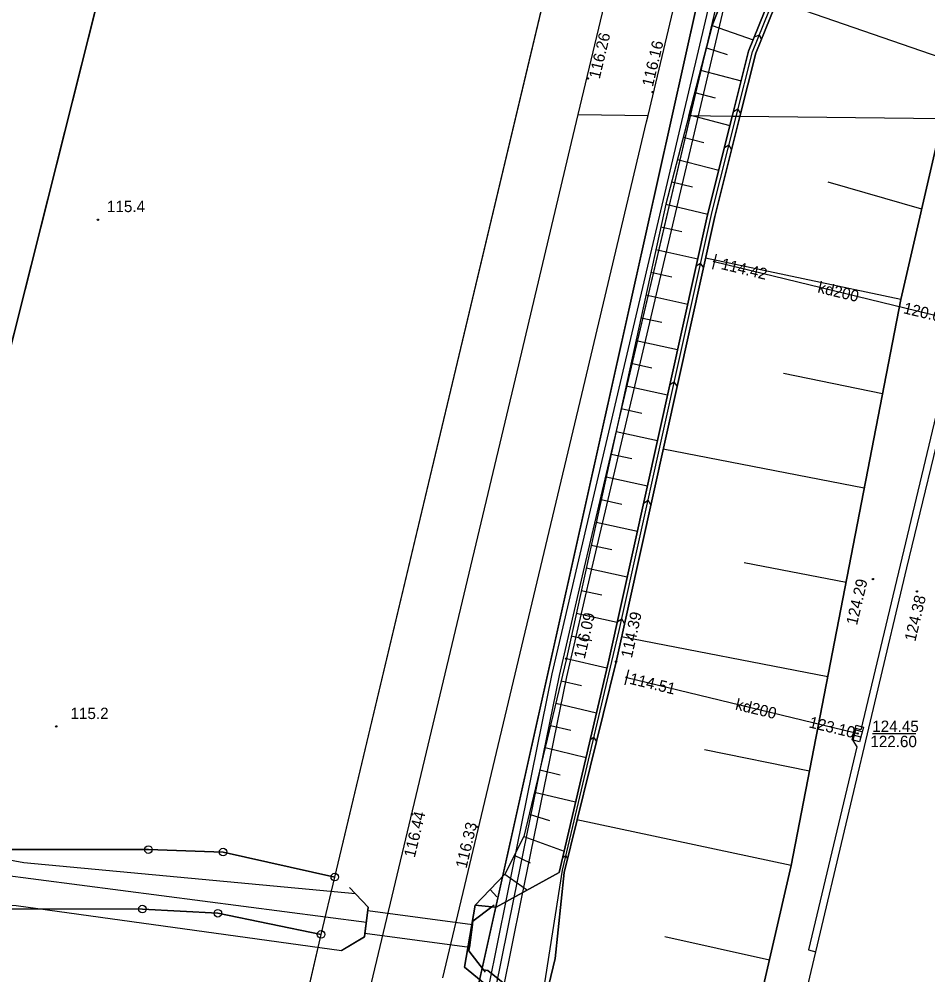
# Model space of a CAD drawing. Extents: x 6424617 to 6425697, y 5665845 to 5667190.
# Drawn here: x 6425223.5 to 6425283.4, y 5666258.5 to 5666321.5 of the extents above; entities that cross this region are included whole.
import ezdxf

# ---------------------------------------------------------------- set-up
doc = ezdxf.new("R2010")
doc.units = 0
for name, color, linetype in [('Warstwa 1', 7, 'Continuous'), ('Warstwa 10', 7, 'Continuous'), ('Warstwa 12', 7, 'Continuous'), ('Warstwa 13', 7, 'Continuous'), ('Warstwa 14', 7, 'Continuous'), ('Warstwa 15', 7, 'Continuous'), ('Warstwa 20', 7, 'Continuous'), ('Warstwa 21', 7, 'Continuous'), ('Warstwa 22', 7, 'Continuous'), ('Warstwa 25', 7, 'Continuous'), ('Warstwa 4', 7, 'Continuous'), ('Warstwa 47', 7, 'Continuous'), ('Warstwa 6', 7, 'Continuous'), ('Warstwa 61', 7, 'Continuous'), ('Warstwa 8', 7, 'Continuous'), ('Warstwa 9', 7, 'Continuous')]:
    doc.layers.add(name, color=color, linetype=linetype)

msp = doc.modelspace()

# ---------------------------------------------------------------- linework, layer by layer
at = {"layer": 'Warstwa 1'}
for p, q in [((6425217.631, 5666278.959), (6425251.855, 5666415.084)), ((6425217.631, 5666278.959), (6425251.855, 5666415.084)), ((6425244.275, 5666264.977), (6425279.037, 5666410.906)), ((6425244.275, 5666264.977), (6425279.037, 5666410.906)), ((6425252.81, 5666253.65), (6425268.93, 5666326.03)), ((6425252.81, 5666253.65), (6425268.93, 5666326.03)), ((6425221.085, 5666266.797), (6425231.986, 5666266.785)), ((6425221.085, 5666266.797), (6425231.986, 5666266.785)), ((6425231.986, 5666266.785), (6425236.914, 5666266.626)), ((6425231.986, 5666266.785), (6425236.914, 5666266.626)), ((6425236.914, 5666266.626), (6425244.275, 5666264.977)), ((6425236.914, 5666266.626), (6425244.275, 5666264.977)), ((6425243.369, 5666261.198), (6425244.275, 5666264.977)), ((6425243.369, 5666261.198), (6425244.275, 5666264.977)), ((6425220.398, 5666262.875), (6425231.589, 5666262.87)), ((6425220.398, 5666262.875), (6425231.589, 5666262.87)), ((6425231.589, 5666262.87), (6425236.566, 5666262.59)), ((6425231.589, 5666262.87), (6425236.566, 5666262.59)), ((6425236.566, 5666262.59), (6425243.369, 5666261.198)), ((6425236.566, 5666262.59), (6425243.369, 5666261.198)), ((6425235.255, 5666226.065), (6425243.369, 5666261.198)), ((6425235.255, 5666226.065), (6425243.369, 5666261.198))]:
    msp.add_line(p, q, dxfattribs=at)
at = {"layer": 'Warstwa 10'}
for points in [[(6425267.728, 5666315.146), (6425271.19, 5666329.86), (6425276.57, 5666352.13), (6425283.28, 5666380.44), (6425290.28, 5666409.92), (6425300.88, 5666454.64), (6425307.494, 5666481.767)], [(6425253.995, 5666253.473), (6425254.27, 5666254.64), (6425254.89, 5666257.65), (6425256.08, 5666263.53), (6425259.08, 5666278.27), (6425260.73, 5666285.4), (6425267.728, 5666315.146)], [(6425245.24, 5666264.28), (6425246.48, 5666262.99), (6425246.23, 5666261.04), (6425244.69, 5666260.12)], [(6425254.2, 5666258.71), (6425253.12, 5666260.12), (6425253.37, 5666262.07), (6425254.79, 5666263.15)]]:
    msp.add_lwpolyline(points, dxfattribs=at)
for centre in [(6425231.986, 5666266.785), (6425231.986, 5666266.785), (6425236.914, 5666266.626), (6425236.914, 5666266.626), (6425244.275, 5666264.977), (6425244.275, 5666264.977), (6425231.589, 5666262.87), (6425236.566, 5666262.59), (6425243.369, 5666261.198), (6425243.369, 5666261.198)]:
    msp.add_circle(centre, 0.25, dxfattribs=at)
at = {"layer": 'Warstwa 12'}
for points in [[(6425269.29, 5666305.54), (6425285.02, 5666301.73), (6425285.27, 5666301.67)], [(6425263.52, 5666278.14), (6425278.51, 5666274.5), (6425278.75, 5666274.44)]]:
    msp.add_lwpolyline(points, dxfattribs=at)
at = {"layer": 'Warstwa 13'}
for centre in [(6425228.656, 5666308.303), (6425225.915, 5666274.903)]:
    msp.add_circle(centre, 0.045, dxfattribs=at)
at = {"layer": 'Warstwa 14'}
msp.add_line((6425282.565, 5666274.414), (6425279.727, 5666274.414), dxfattribs=at)
for centre in [(6425269.29, 5666305.54), (6425263.52, 5666278.14), (6425278.51, 5666274.5), (6425278.75, 5666274.44)]:
    msp.add_circle(centre, 0.045, dxfattribs=at)
at = {"layer": 'Warstwa 20'}
for points in [[(6425292.365, 5666377.252), (6425289.64, 5666377.785), (6425288.462, 5666378.016), (6425285.098, 5666378.674), (6425284.514, 5666374.573), (6425281.056, 5666360.861), (6425274.474, 5666334.861), (6425272.279, 5666329.059), (6425269.154, 5666321.093), (6425267.61, 5666315.147)], [(6425242.611, 5666194.491), (6425255.097, 5666192.415), (6425259.987, 5666203.38), (6425274.357, 5666265.741), (6425281.592, 5666303.052), (6425284.331, 5666314.945)], [(6425267.61, 5666315.147), (6425266.101, 5666309.334), (6425259.538, 5666279.373), (6425256.735, 5666267.65), (6425255.48, 5666265.172), (6425253.533, 5666263.126)], [(6425242.611, 5666194.491), (6425238.381, 5666195.698), (6425239.081, 5666197.896), (6425243.343, 5666206.271), (6425244.956, 5666211.914), (6425249.351, 5666232.612), (6425254.77, 5666257.432), (6425252.819, 5666259.028), (6425253.533, 5666263.126)]]:
    msp.add_lwpolyline(points, dxfattribs=at)
at = {"layer": 'Warstwa 21'}
for p, q in [((6425269.408, 5666306.026), (6425269.172, 5666305.054)), ((6425263.638, 5666278.626), (6425263.402, 5666277.654))]:
    msp.add_line(p, q, dxfattribs=at)
for points in [[(6425270.982, 5666315.107), (6425272.032, 5666319.27), (6425277.811, 5666333.541), (6425285.262, 5666361.705), (6425288.33, 5666373.734), (6425289.376, 5666376.843), (6425292.365, 5666377.252), (6425292.98, 5666380.282), (6425290.684, 5666381.655), (6425291.516, 5666385.64), (6425292.444, 5666389.955), (6425293.272, 5666396.442), (6425293.428, 5666397.92), (6425295.255, 5666405.439), (6425296.508, 5666407.837), (6425298.975, 5666417.006), (6425304.639, 5666439.871), (6425307.108, 5666449.766)], [(6425292.365, 5666377.252), (6425289.376, 5666376.843), (6425288.222, 5666377.14), (6425287.852, 5666373.863), (6425284.784, 5666361.834), (6425277.334, 5666333.689), (6425271.555, 5666319.419), (6425270.472, 5666315.113)], [(6425242.611, 5666194.491), (6425241.54, 5666196.131), (6425241.838, 5666198.266), (6425245.305, 5666204.665), (6425246.454, 5666206.825), (6425247.076, 5666209.095), (6425251.913, 5666231.035), (6425258.791, 5666259.61), (6425259.384, 5666265.281), (6425262.815, 5666279.174), (6425269.317, 5666308.506), (6425270.982, 5666315.107)], [(6425253.533, 5666263.126), (6425254.619, 5666263.02), (6425254.911, 5666262.991), (6425259.063, 5666265.277), (6425262.337, 5666279.282), (6425268.839, 5666308.615), (6425270.472, 5666315.113)], [(6425242.611, 5666194.491), (6425241.54, 5666196.131), (6425240.763, 5666196.325), (6425241.403, 5666198.514), (6425244.869, 5666204.893), (6425245.978, 5666207.014), (6425246.598, 5666209.224), (6425251.435, 5666231.143), (6425257.481, 5666256.312), (6425254.356, 5666258.83), (6425254.081, 5666258.865)]]:
    msp.add_lwpolyline(points, dxfattribs=at)
at = {"layer": 'Warstwa 22'}
msp.add_lwpolyline([(6425246.452, 5666262.77), (6425253.342, 5666261.851), (6425253.148, 5666260.34), (6425246.258, 5666261.259)], close=True, dxfattribs=at)
at = {"layer": 'Warstwa 25'}
for centre in [(6425260.968, 5666317.61), (6425265.234, 5666316.712), (6425279.749, 5666284.62), (6425282.645, 5666283.807), (6425259.538, 5666279.373), (6425262.815, 5666279.174), (6425249.37, 5666269.113), (6425253.636, 5666268.296)]:
    msp.add_circle(centre, 0.045, dxfattribs=at)
at = {"layer": 'Warstwa 4'}
for p, q in [((6425278.948, 5666274.208), (6425278.464, 5666274.333)), ((6425279.036, 5666274.547), (6425278.552, 5666274.672))]:
    msp.add_line(p, q, dxfattribs=at)
msp.add_lwpolyline([(6425279.117, 5666274.862), (6425278.867, 5666273.893), (6425278.383, 5666274.018), (6425278.633, 5666274.987)], close=True, dxfattribs=at)
at = {"layer": 'Warstwa 47'}
msp.add_lwpolyline([(6425284.331, 5666314.945), (6425281.592, 5666303.052), (6425274.357, 5666265.741), (6425259.987, 5666203.38), (6425255.097, 5666192.415), (6425253.98, 5666187.623), (6425253.35, 5666184.874), (6425252.002, 5666166.702), (6425239.735, 5666105.594), (6425235.312, 5666094.44), (6425233.454, 5666084.61), (6425233.542, 5666070.604), (6425233.206, 5666068.64), (6425232.731, 5666065.562)], dxfattribs=at)
at = {"layer": 'Warstwa 6'}
for points in [[(6425294.11, 5666422.45), (6425272.8, 5666335.34), (6425268.93, 5666326.03), (6425252.81, 5666253.65), (6425242.84, 5666212.49), (6425237.49, 5666195.18)], [(6425294.11, 5666422.45), (6425272.8, 5666335.34), (6425268.93, 5666326.03), (6425252.81, 5666253.65), (6425242.84, 5666212.49), (6425237.49, 5666195.18)], [(6425227.334, 5666191.99), (6425232.133, 5666212.582), (6425235.255, 5666226.065), (6425243.369, 5666261.198), (6425244.275, 5666264.977), (6425279.037, 5666410.906)], [(6425285.961, 5666301.803), (6425285.134, 5666301.998), (6425284.95, 5666301.211), (6425285.193, 5666300.807), (6425278.94, 5666274.691), (6425278.611, 5666274.767), (6425278.427, 5666273.98), (6425278.679, 5666273.565), (6425275.497, 5666260.179), (6425275.985, 5666260.06)], [(6425220.398, 5666262.875), (6425231.589, 5666262.87), (6425236.566, 5666262.59), (6425243.369, 5666261.198), (6425244.275, 5666264.977), (6425236.914, 5666266.626), (6425231.986, 5666266.785), (6425221.085, 5666266.797)]]:
    msp.add_lwpolyline(points, dxfattribs=at)
for points in [[(6425218.458, 5666377.355), (6425219.657, 5666368.17), (6425220.198, 5666359.913), (6425221.104, 5666334.73), (6425218.676, 5666314.978), (6425216.007, 5666295.17), (6425216.425, 5666279.284), (6425217.156, 5666267.745), (6425217.631, 5666278.959), (6425251.855, 5666415.084), (6425212.702, 5666415.917), (6425203.098, 5666416.433), (6425205.496, 5666411.333), (6425216.648, 5666385.677)], [(6425217.631, 5666278.959), (6425217.156, 5666267.745), (6425221.085, 5666266.797), (6425231.986, 5666266.785), (6425236.914, 5666266.626), (6425244.275, 5666264.977), (6425279.037, 5666410.906), (6425251.855, 5666415.084)], [(6425243.369, 5666261.198), (6425236.566, 5666262.59), (6425231.589, 5666262.87), (6425220.398, 5666262.875), (6425213.713, 5666263.366), (6425199.014, 5666263.504), (6425165.793, 5666264.485), (6425154.239, 5666265.014), (6425144.542, 5666264.551), (6425131.542, 5666263.798), (6425122.851, 5666227.251), (6425235.255, 5666226.065)]]:
    msp.add_lwpolyline(points, close=True, dxfattribs=at)
at = {"layer": 'Warstwa 61'}
for points in [[(6425267.728, 5666315.146), (6425267.754, 5666315.255), (6425271.19, 5666329.86), (6425276.57, 5666352.13), (6425283.28, 5666380.44), (6425290.28, 5666409.92), (6425300.88, 5666454.64), (6425306.981, 5666479.664), (6425307.494, 5666481.768)], [(6425214.289, 5666065.784), (6425214.304, 5666065.867), (6425214.578, 5666067.388), (6425214.582, 5666067.413), (6425215.83, 5666077.04), (6425215.86, 5666083.8), (6425216.52, 5666087.79), (6425219.61, 5666105.3), (6425228.34, 5666144.71), (6425232.26, 5666162.7), (6425238.65, 5666194.71), (6425242.26, 5666206.57), (6425245.38, 5666217.85), (6425248.88, 5666231.8), (6425254.27, 5666254.64), (6425254.89, 5666257.65), (6425256.08, 5666263.53), (6425259.08, 5666278.27), (6425260.73, 5666285.399), (6425260.73, 5666285.401), (6425267.702, 5666315.037), (6425267.728, 5666315.146)]]:
    msp.add_lwpolyline(points, dxfattribs=at)
at = {"layer": 'Warstwa 8'}
for p, q in [((6425264.928, 5666315.18), (6425268.54, 5666330.327)), ((6425260.318, 5666315.235), (6425263.693, 5666329.424)), ((6425259.99, 5666313.856), (6425260.318, 5666315.235)), ((6425260.318, 5666315.235), (6425264.928, 5666315.18)), ((6425260.318, 5666315.235), (6425264.928, 5666315.18)), ((6425260.661, 5666297.248), (6425264.828, 5666314.759)), ((6425264.828, 5666314.759), (6425264.928, 5666315.18)), ((6425256.288, 5666298.288), (6425259.99, 5666313.856)), ((6425281.983, 5666285.35), (6425285.955, 5666301.804)), ((6425252.111, 5666280.777), (6425256.288, 5666298.288)), ((6425256.494, 5666279.738), (6425260.661, 5666297.248)), ((6425275.985, 5666260.06), (6425281.983, 5666285.35)), ((6425247.478, 5666261.315), (6425252.111, 5666280.777)), ((6425251.396, 5666258.333), (6425256.494, 5666279.738)), ((6425243.776, 5666245.746), (6425247.478, 5666261.315)), ((6425273.018, 5666247.559), (6425275.985, 5666260.06))]:
    msp.add_line(p, q, dxfattribs=at)
for points in [[(6425307.521, 5666483.989), (6425300.394, 5666454.757), (6425289.794, 5666410.035), (6425282.794, 5666380.555), (6425276.084, 5666352.246), (6425270.704, 5666329.976), (6425267.215, 5666315.152)], [(6425268.241, 5666315.14), (6425271.676, 5666329.744), (6425277.056, 5666352.014), (6425283.766, 5666380.325), (6425290.766, 5666409.805), (6425301.366, 5666454.523), (6425307.467, 5666479.546)], [(6425267.215, 5666315.152), (6425260.243, 5666285.514), (6425258.591, 5666278.376), (6425255.59, 5666263.629), (6425254.4, 5666257.75), (6425253.782, 5666254.748), (6425248.394, 5666231.918), (6425244.896, 5666217.978), (6425241.78, 5666206.709), (6425238.164, 5666194.832), (6425231.771, 5666162.802), (6425227.852, 5666144.817), (6425219.119, 5666105.398), (6425216.027, 5666087.874), (6425215.36, 5666083.842), (6425215.33, 5666077.073), (6425214.086, 5666067.477), (6425213.782, 5666065.79)], [(6425214.796, 5666065.778), (6425215.074, 5666067.323), (6425216.33, 5666077.007), (6425216.36, 5666083.758), (6425217.013, 5666087.706), (6425220.101, 5666105.202), (6425228.828, 5666144.603), (6425232.749, 5666162.598), (6425239.136, 5666194.588), (6425242.74, 5666206.431), (6425245.864, 5666217.722), (6425249.366, 5666231.682), (6425254.758, 5666254.532), (6425255.38, 5666257.55), (6425256.57, 5666263.431), (6425259.569, 5666278.164), (6425261.217, 5666285.286), (6425268.241, 5666315.14)]]:
    msp.add_lwpolyline(points, dxfattribs=at)
at = {"layer": 'Warstwa 9'}
for p, q in [((6425271.812, 5666319.378), (6425277.578, 5666333.658)), ((6425285.185, 5666318.653), (6425273.42, 5666322.698)), ((6425269.154, 5666321.093), (6425271.851, 5666320.15)), ((6425271.935, 5666320.357), (6425272.264, 5666320.497)), ((6425272.4, 5666320.178), (6425272.264, 5666320.497)), ((6425268.772, 5666319.623), (6425270.139, 5666319.189)), ((6425270.727, 5666315.11), (6425271.812, 5666319.378)), ((6425268.391, 5666318.153), (6425271.062, 5666317.46)), ((6425268.009, 5666316.683), (6425269.35, 5666316.335)), ((6425270.55, 5666315.425), (6425270.853, 5666315.604)), ((6425271.032, 5666315.303), (6425270.853, 5666315.604)), ((6425267.627, 5666315.214), (6425267.897, 5666315.144)), ((6425267.897, 5666315.144), (6425270.322, 5666314.514)), ((6425269.144, 5666308.842), (6425270.727, 5666315.11)), ((6425267.246, 5666313.744), (6425268.599, 5666313.393)), ((6425269.955, 5666313.057), (6425270.253, 5666313.235)), ((6425270.434, 5666312.933), (6425270.253, 5666313.235)), ((6425266.864, 5666312.274), (6425269.582, 5666311.569)), ((6425266.482, 5666310.804), (6425267.85, 5666310.463)), ((6425282.962, 5666308.999), (6425276.802, 5666310.769)), ((6425266.101, 5666309.334), (6425268.854, 5666308.675)), ((6425267.082, 5666299.552), (6425269.144, 5666308.842)), ((6425265.773, 5666307.836), (6425267.15, 5666307.52)), ((6425265.445, 5666306.338), (6425268.201, 5666305.735)), ((6425268.095, 5666305.258), (6425268.391, 5666305.446)), ((6425268.575, 5666305.157), (6425268.391, 5666305.446)), ((6425281.592, 5666303.052), (6425268.712, 5666305.778)), ((6425265.116, 5666304.84), (6425266.493, 5666304.539)), ((6425264.788, 5666303.342), (6425267.537, 5666302.741)), ((6425264.46, 5666301.844), (6425265.832, 5666301.544)), ((6425264.132, 5666300.346), (6425266.873, 5666299.746)), ((6425263.014, 5666281.218), (6425267.082, 5666299.552)), ((6425263.804, 5666298.848), (6425265.172, 5666298.548)), ((6425266.362, 5666297.441), (6425266.655, 5666297.628)), ((6425266.841, 5666297.337), (6425266.655, 5666297.628)), ((6425280.386, 5666296.834), (6425273.851, 5666298.158)), ((6425263.476, 5666297.35), (6425266.209, 5666296.752)), ((6425263.148, 5666295.852), (6425264.512, 5666295.553)), ((6425262.819, 5666294.353), (6425265.546, 5666293.758)), ((6425279.18, 5666290.615), (6425265.921, 5666293.187)), ((6425262.491, 5666292.855), (6425263.852, 5666292.558)), ((6425262.163, 5666291.357), (6425264.882, 5666290.762)), ((6425261.835, 5666289.859), (6425263.193, 5666289.562)), ((6425264.63, 5666289.624), (6425264.921, 5666289.81)), ((6425265.108, 5666289.516), (6425264.921, 5666289.81)), ((6425261.507, 5666288.361), (6425264.218, 5666287.768)), ((6425261.179, 5666286.863), (6425262.532, 5666286.567)), ((6425277.974, 5666284.397), (6425271.262, 5666285.698)), ((6425260.851, 5666285.365), (6425263.554, 5666284.774)), ((6425260.522, 5666283.867), (6425261.872, 5666283.572)), ((6425260.194, 5666282.369), (6425262.89, 5666281.779)), ((6425262.897, 5666281.807), (6425263.186, 5666281.991)), ((6425263.374, 5666281.696), (6425263.186, 5666281.991)), ((6425259.287, 5666265.438), (6425263.014, 5666281.218)), ((6425259.866, 5666280.871), (6425261.209, 5666280.57)), ((6425276.769, 5666278.178), (6425263.179, 5666280.814)), ((6425259.538, 5666279.373), (6425262.215, 5666278.761)), ((6425259.188, 5666277.908), (6425260.528, 5666277.594)), ((6425258.837, 5666276.442), (6425261.523, 5666275.801)), ((6425258.487, 5666274.977), (6425259.833, 5666274.655)), ((6425261.113, 5666274.045), (6425261.356, 5666274.195)), ((6425261.52, 5666273.929), (6425261.356, 5666274.195)), ((6425258.136, 5666273.512), (6425260.837, 5666272.866)), ((6425275.563, 5666271.96), (6425268.636, 5666273.369)), ((6425257.786, 5666272.046), (6425259.14, 5666271.723)), ((6425257.436, 5666270.581), (6425260.151, 5666269.933)), ((6425257.086, 5666269.116), (6425258.428, 5666268.71)), ((6425274.357, 5666265.741), (6425260.239, 5666268.744)), ((6425256.735, 5666267.65), (6425259.39, 5666266.675)), ((6425256.108, 5666266.411), (6425257.143, 5666265.905)), ((6425259.294, 5666266.264), (6425259.515, 5666266.401)), ((6425259.619, 5666266.232), (6425259.515, 5666266.401)), ((6425215.311, 5666266.049), (6425246.355, 5666262.015)), ((6425255.48, 5666265.172), (6425256.967, 5666264.123)), ((6425258.019, 5666257.302), (6425259.287, 5666265.438)), ((6425254.506, 5666264.149), (6425254.948, 5666263.682)), ((6425272.92, 5666259.505), (6425266.023, 5666261.032))]:
    msp.add_line(p, q, dxfattribs=at)
for points in [[(6425306.496, 5666399.029), (6425300.821, 5666375.348), (6425289.41, 5666327.719), (6425285.185, 5666318.653), (6425284.331, 5666314.945), (6425270.982, 5666315.107), (6425272.032, 5666319.27), (6425277.811, 5666333.541), (6425285.262, 5666361.705), (6425288.33, 5666373.734), (6425289.376, 5666376.843), (6425292.365, 5666377.252), (6425292.98, 5666380.282), (6425290.684, 5666381.655), (6425291.516, 5666385.64), (6425292.444, 5666389.955), (6425293.272, 5666396.442), (6425293.428, 5666397.92), (6425295.255, 5666405.439), (6425296.508, 5666407.837), (6425298.975, 5666417.006), (6425304.639, 5666439.871), (6425307.108, 5666449.766)], [(6425285.098, 5666378.674), (6425288.462, 5666378.016), (6425289.64, 5666377.785), (6425292.365, 5666377.252), (6425289.376, 5666376.843), (6425288.222, 5666377.14), (6425287.852, 5666373.863), (6425284.784, 5666361.834), (6425277.334, 5666333.689), (6425271.555, 5666319.419), (6425270.472, 5666315.113), (6425267.61, 5666315.147), (6425269.154, 5666321.093), (6425272.279, 5666329.059), (6425274.474, 5666334.861), (6425281.056, 5666360.861), (6425284.514, 5666374.573)], [(6425270.472, 5666315.113), (6425271.555, 5666319.419), (6425277.334, 5666333.689), (6425284.784, 5666361.834), (6425287.852, 5666373.863), (6425288.222, 5666377.14), (6425289.376, 5666376.843), (6425288.33, 5666373.734), (6425285.262, 5666361.705), (6425277.811, 5666333.541), (6425272.032, 5666319.27), (6425270.982, 5666315.107)], [(6425242.611, 5666194.491), (6425255.097, 5666192.415), (6425259.987, 5666203.38), (6425274.357, 5666265.741), (6425281.592, 5666303.052), (6425284.331, 5666314.945), (6425270.982, 5666315.107), (6425269.317, 5666308.506), (6425262.815, 5666279.174), (6425259.384, 5666265.281), (6425258.791, 5666259.61), (6425251.913, 5666231.035), (6425247.076, 5666209.095), (6425246.454, 5666206.825), (6425245.305, 5666204.665), (6425241.838, 5666198.266), (6425241.54, 5666196.131)], [(6425253.533, 5666263.126), (6425254.619, 5666263.02), (6425254.911, 5666262.991), (6425259.063, 5666265.277), (6425262.337, 5666279.282), (6425268.839, 5666308.615), (6425270.472, 5666315.113), (6425267.61, 5666315.147), (6425266.101, 5666309.334), (6425259.538, 5666279.373), (6425256.735, 5666267.65), (6425255.48, 5666265.172)], [(6425253.533, 5666263.126), (6425252.819, 5666259.028), (6425254.77, 5666257.432), (6425249.351, 5666232.612), (6425244.956, 5666211.914), (6425243.343, 5666206.271), (6425239.081, 5666197.896), (6425238.381, 5666195.698), (6425242.611, 5666194.491), (6425241.54, 5666196.131), (6425240.763, 5666196.325), (6425241.403, 5666198.514), (6425244.869, 5666204.893), (6425245.978, 5666207.014), (6425246.598, 5666209.224), (6425251.435, 5666231.143), (6425257.481, 5666256.312), (6425254.356, 5666258.83), (6425254.081, 5666258.865), (6425253.12, 5666260.12), (6425253.37, 5666262.07), (6425254.619, 5666263.02)]]:
    msp.add_lwpolyline(points, close=True, dxfattribs=at)
for points in [[(6425251.913, 5666231.035), (6425258.791, 5666259.61), (6425259.384, 5666265.281), (6425262.815, 5666279.174), (6425269.317, 5666308.506), (6425270.982, 5666315.107), (6425270.472, 5666315.113), (6425268.839, 5666308.615), (6425262.337, 5666279.282), (6425259.063, 5666265.277), (6425254.911, 5666262.991), (6425254.619, 5666263.02), (6425253.37, 5666262.07), (6425253.12, 5666260.12), (6425254.081, 5666258.865), (6425254.356, 5666258.83), (6425257.481, 5666256.312)], [(6425075.813, 5666260.95), (6425091.512, 5666262.148), (6425134.575, 5666264.204), (6425180.978, 5666264.874), (6425215.178, 5666263.695), (6425223.265, 5666263.098), (6425244.727, 5666260.142), (6425246.23, 5666261.04), (6425246.48, 5666262.99), (6425245.635, 5666263.869), (6425223.787, 5666265.925), (6425217.834, 5666267.009), (6425216.925, 5666268.141), (6425213.213, 5666267.955), (6425181.259, 5666268.82), (6425134.514, 5666268.7), (6425091.188, 5666267.036), (6425075.666, 5666266.182)]]:
    msp.add_lwpolyline(points, dxfattribs=at)

# ---------------------------------------------------------------- texts
at = {"layer": 'Warstwa 13'}
for s, p in [('115.4', (6425229.257, 5666308.805)), ('115.2', (6425226.854, 5666275.392))]:
    msp.add_text(s, height=0.75, dxfattribs=at).set_placement(p)
for rotation, p in [(346.38164, (6425276.058, 5666303.515)), (346.35299, (6425270.633, 5666276.027))]:
    msp.add_text('kd200', height=0.75, rotation=rotation, dxfattribs=at).set_placement(p)
at = {"layer": 'Warstwa 14'}
for s, rotation, p in [('114.42', 346.38164, (6425269.688, 5666305.058)), ('120.60', 346.38164, (6425281.703, 5666302.147)), ('114.51', 346.35299, (6425263.648, 5666277.723)), ('123.10', 346.35299, (6425275.483, 5666274.849))]:
    msp.add_text(s, height=0.75, rotation=rotation, dxfattribs=at).set_placement(p)
msp.add_text('122.60', height=0.75, dxfattribs=at).set_placement((6425279.578, 5666273.539))
at = {"layer": 'Warstwa 15'}
msp.add_text('124.45', height=0.75, dxfattribs=at).set_placement((6425279.702, 5666274.539))
at = {"layer": 'Warstwa 25'}
for s, rotation, p in [('116.26', 76.62165, (6425261.736, 5666317.543)), ('116.16', 76.58727, (6425265.238, 5666317.022)), ('124.29', 76.65602, (6425278.695, 5666281.539)), ('124.38', 76.65602, (6425282.541, 5666280.466)), ('116.09', 76.97115, (6425260.745, 5666279.318)), ('114.39', 77.504, (6425263.853, 5666279.37)), ('116.44', 76.61019, (6425249.544, 5666266.216)), ('116.33', 76.60446, (6425252.951, 5666265.505))]:
    msp.add_text(s, height=0.75, rotation=rotation, dxfattribs=at).set_placement(p)

doc.saveas('drawing.dxf')
